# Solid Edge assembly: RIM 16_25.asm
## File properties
Title: Zylinder
Author: ahadarics
Template: iso metric assembly.asm
Last saved by: ahadarics
Revision: 7
Application: Solid Edge
Username: ahadarics
Dokumentum tartalom típus: 1
Document Number: RIM 16/25
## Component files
Profilrohr.par
Kolbenstange.par
Kit_1.par
Kit_2.par
Mutter_1.par
Mutter_2.par
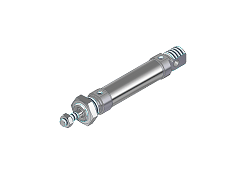
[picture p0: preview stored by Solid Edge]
